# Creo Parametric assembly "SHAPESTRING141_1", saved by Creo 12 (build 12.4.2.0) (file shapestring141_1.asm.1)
Units: Custom; MM, KILOGRAM, SECS

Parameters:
  PTC_WM_ITERATION = "0"
  PTC_WM_VERSION = "-.0"
  PTC_WM_LIFECYCLE_STATE = "In Work"
  PTC_WM_LIFECYCLE = "MO_CADDocument"
  PTC_WM_CREATED_BY = "Maximilian Roepper (Z0017RMS: MO)"
  PTC_WM_CREATED_ON = "18-Sep-26 11:36:42 AM"
  PTC_WM_MODIFIED_BY = "Maximilian Roepper (Z0017RMS: MO)"
  PTC_WM_MODIFIED_ON = "18-Sep-26 11:36:46 AM"
  PDMLINKNUMBER = "PDM000071455068"
  PTC_WM_NUMBER = "PDM000071455068"

Other parameters: WEIGHT, WEIGHT_FACTOR, WEIGHT_ADD, MC_ERRORS, SUPPLIER

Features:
  1. coordinate system
  2. imported feature
  3. component "SHAPESTRING072_1"
  4. component "SHAPESTRING133_1"
  5. component "SHAPESTRING134_1"
  6. component "SHAPESTRING135_1"
  7. component "SHAPESTRING136_1"
  8. component "SHAPESTRING137_1"
  9. component "SHAPESTRING138_1"
  10. component "SHAPESTRING139_1"
  11. component "SHAPESTRING140_1"

Other named items: DRW_VIEW_ORG, ROUGH-GROB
